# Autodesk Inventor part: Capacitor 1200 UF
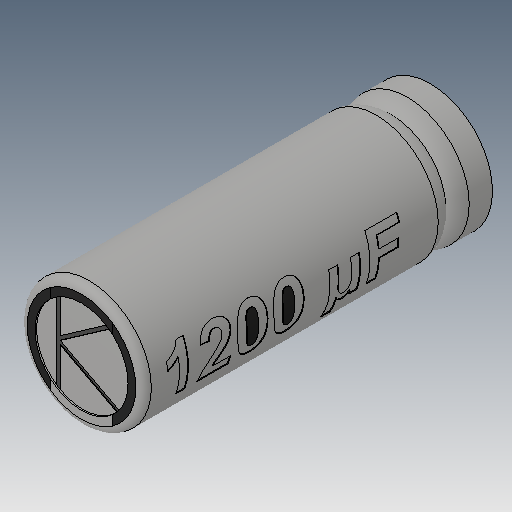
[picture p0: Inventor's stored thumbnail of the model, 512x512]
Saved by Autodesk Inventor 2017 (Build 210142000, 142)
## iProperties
Created: 2005-12
Part Number: Capacitor 1200 UF
Material: Generic
Document SubType Name: Modeling
Designer: DanielSeverino
Density: 1 g/cm^3
Appearance: Default
Author: DanielSeverino
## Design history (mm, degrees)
feature "Solid1"
body "Solid2"
